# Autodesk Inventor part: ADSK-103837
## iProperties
Shininess: 20.0
Created: 2001-04
Part Number: ADSK-103837
Document SubType Name: Modeling
Designer: Administrator
Stock Number: ADSK-103837
Density: 1 g/cm^3
Density: 0.0
Volumn: 0.0
Area: 0.0
PropertySet Name: Model Information
Control State: 0
Master: False
Checked Out: False
Author: Administrator
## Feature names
1. Revolution1
